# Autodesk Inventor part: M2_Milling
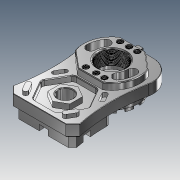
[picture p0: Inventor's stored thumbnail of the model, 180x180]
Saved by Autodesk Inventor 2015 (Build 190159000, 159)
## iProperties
Created: 2015-04
Part Number: M2_Milling
Material: Aço
Document SubType Name: Modeling
Designer: Andrew Almeida
Density: 7.85 g/cm^3
Appearance: Placa
Title: C:/Users/Andrew Almeida/Documents/Projeto WS2015/WS2015 CAD Data ANLAS/07/#07 - CNC Milling/01 - 3D Models/M2_Milling.stp
Creation Date: 2015-04-23
Sending System: Autodesk Translation Framework v4.0.0.5211
Preprocessor: ST-DEVELOPER v16.1
Author: Andrew Almeida
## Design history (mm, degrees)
node "M2_Milling1"
feature "Rosca1" dims "d0" = 10, "d1" = 0
feature "Rosca2" dims "d2" = 10, "d3" = 0
feature "Rosca3" dims "d4" = 10, "d5" = 0
feature "Rosca4" dims "d6" = 10, "d7" = 0
feature "Rosca5" dims "d8" = 10, "d9" = 0
feature "Rosca6" dims "d10" = 10, "d11" = 0
feature "Rosca7" dims "d12" = 20, "d13" = 0
feature "Rosca8" dims "d14" = 10, "d15" = 0
feature "Rosca9" dims "d16" = 10, "d17" = 0
feature "Rosca10" dims "d18" = 10, "d19" = 0
sketch "Esboço2"
  geometry: L1 (4.188, 0)-(4.188, 22); L2 (4.188, 22)-(3.447, 22); L3 (3.447, 22)-(3.447, 0); L4 (3.447, 0)-(4.188, 0); L5 (0, -10.409)-(0, 54.818) reference
  constraints: 8 end point
revolve "Revolução1" sketch "Esboço2" stored, may be unused: angle "d29" = 0 deg
sketch "Esboço1"
  geometry: L1 (-0.583, -0.051)-(-0.5, -0.051); L2 (0.083, -0.691)-(0, -0.851); L3 (-1, -0.851)-(-1.083, -0.691); L4 (-0.417, -0.051)-(-0.5, 0.109); L5 (-0.5, 0.109)-(-0.583, -0.051); L6 (-1, -0.851)-(-0.917, -0.691); L7 (-0.417, -0.051)-(-0.083, -0.691); L8 (-1.083, -0.691)-(-0.917, -0.691); L9 (0.083, -0.691)-(-0.083, -0.691); L10 (-1, -0.851)-(-1, -0.691); L11 (0, -0.851)-(0, -0.691); L12 (-0.5, 0.109)-(-0.5, 0); L13 (-1, -0.742)-(0, -0.742); L14 (-0.083, -0.691)-(0, -0.851); L15 (-0.917, -0.691)-(-0.583, -0.051); L16 (0, 0)-(0, 0.018); L17 (0, 0.018)-(0, 0); L18 (0, 0)-(0.033, 0); L19 (-0.5, 0)-(-0.5, -0.051); L20 (-0.5, -0.051)-(-0.417, -0.051); A1 r 0.094 centre (-1, -0.648) between (-1.083, -0.691) and (-1, -0.742); A2 r 0.094 centre (-1, -0.648) between (-1, -0.742) and (-0.917, -0.691); A3 r 0.094 centre (0, -0.648) between (-0.083, -0.691) and (0, -0.742); A4 r 0.094 centre (0, -0.648) between (0, -0.742) and (0.083, -0.691); A5 r 0.094 centre (-0.5, -0.094) between (-0.5, 0) and (-0.583, -0.051); A6 r 0.094 centre (-0.5, -0.094) between (-0.417, -0.051) and (-0.5, 0)
  constraints: 40 end point, 12 point on circle, 10 parallel, 8 tangent, 6 centre point, 6 collinear, 2 midpoint, 2 point on line, 1 horizontal, 1 perpendicular, 3 other
  dimensions: "d20" = 55 deg angle of L7 L15 (= d27); "d21" = 0.16008 distance of L4.end L1.end (= 0.160083 x Esboço1_Pitch); "d22" = 0.16008 distance of L2.end L11.end (= 0.160083 x Esboço1_Pitch); "Esboço1_ThreadOffset" = 0 distance between parallel lines of L16 L11; "Esboço1_MajorRadius" = 0.74146 distance from line of L13 L16.start; "d25" = 1 distance from line of L2.end L10 (= Esboço1_Pitch); "Esboço1_MinorRadius" = 0 distance edge to line of A6 L18 (derived)
feature "Espiral1" sketch "Esboço1" pitch "d30" = 1.5015; turns "d32" = 1; dims "d31" = 25, "d33" = 0, angle "d34" = 0 deg, angle "d35" = 0 deg, "d36" = 0, "d37" = 0
sketch "Esboço4"
  geometry: L1 (4.188, 0)-(4.188, 22); L2 (4.188, 22)-(3.447, 22); L3 (3.447, 22)-(3.447, 0); L4 (3.447, 0)-(4.188, 0); L5 (0, -10.409)-(0, 54.818) reference
  constraints: 8 end point
revolve "Revolução2" sketch "Esboço4" stored, may be unused: angle "d47" = 0 deg
sketch "Esboço3"
  geometry: L1 (-0.583, -0.051)-(-0.5, -0.051); L2 (0.083, -0.691)-(0, -0.851); L3 (-1, -0.851)-(-1.083, -0.691); L4 (-0.417, -0.051)-(-0.5, 0.109); L5 (-0.5, 0.109)-(-0.583, -0.051); L6 (-1, -0.851)-(-0.917, -0.691); L7 (-0.417, -0.051)-(-0.083, -0.691); L8 (-1.083, -0.691)-(-0.917, -0.691); L9 (0.083, -0.691)-(-0.083, -0.691); L10 (-1, -0.851)-(-1, -0.691); L11 (0, -0.851)-(0, -0.691); L12 (-0.5, 0.109)-(-0.5, 0); L13 (-1, -0.742)-(0, -0.742); L14 (-0.083, -0.691)-(0, -0.851); L15 (-0.917, -0.691)-(-0.583, -0.051); L16 (0, 0)-(0, 0.018); L17 (0, 0.018)-(0, 0); L18 (0, 0)-(0.033, 0); L19 (-0.5, 0)-(-0.5, -0.051); L20 (-0.5, -0.051)-(-0.417, -0.051); A1 r 0.094 centre (-1, -0.648) between (-1.083, -0.691) and (-1, -0.742); A2 r 0.094 centre (-1, -0.648) between (-1, -0.742) and (-0.917, -0.691); A3 r 0.094 centre (0, -0.648) between (-0.083, -0.691) and (0, -0.742); A4 r 0.094 centre (0, -0.648) between (0, -0.742) and (0.083, -0.691); A5 r 0.094 centre (-0.5, -0.094) between (-0.5, 0) and (-0.583, -0.051); A6 r 0.094 centre (-0.5, -0.094) between (-0.417, -0.051) and (-0.5, 0)
  constraints: 40 end point, 12 point on circle, 10 parallel, 8 tangent, 6 centre point, 6 collinear, 2 midpoint, 2 point on line, 1 horizontal, 1 perpendicular, 3 other
  dimensions: "d38" = 55 deg angle of L7 L15 (= d45); "d39" = 0.16008 distance of L4.end L1.end (= 0.160083 x Esboço3_Pitch); "d40" = 0.16008 distance of L2.end L11.end (= 0.160083 x Esboço3_Pitch); "Esboço3_ThreadOffset" = 0 distance between parallel lines of L16 L11; "Esboço3_MajorRadius" = 0.74146 distance from line of L13 L16.start; "d43" = 1 distance from line of L2.end L10 (= Esboço3_Pitch); "Esboço3_MinorRadius" = 0 distance edge to line of A6 L18 (derived)
feature "Espiral2" sketch "Esboço3" pitch "d48" = 1.5015; turns "d50" = 1; dims "d49" = 25, "d51" = 0, angle "d52" = 0 deg, angle "d53" = 0 deg, "d54" = 0, "d55" = 0
sketch "Esboço6"
  geometry: L1 (4.188, 0)-(4.188, 22); L2 (4.188, 22)-(3.447, 22); L3 (3.447, 22)-(3.447, 0); L4 (3.447, 0)-(4.188, 0); L5 (0, -10.409)-(0, 54.818) reference
  constraints: 8 end point
revolve "Revolução3" sketch "Esboço6" stored, may be unused: angle "d65" = 0 deg
sketch "Esboço5"
  geometry: L1 (-0.583, -0.051)-(-0.5, -0.051); L2 (0.083, -0.691)-(0, -0.851); L3 (-1, -0.851)-(-1.083, -0.691); L4 (-0.417, -0.051)-(-0.5, 0.109); L5 (-0.5, 0.109)-(-0.583, -0.051); L6 (-1, -0.851)-(-0.917, -0.691); L7 (-0.417, -0.051)-(-0.083, -0.691); L8 (-1.083, -0.691)-(-0.917, -0.691); L9 (0.083, -0.691)-(-0.083, -0.691); L10 (-1, -0.851)-(-1, -0.691); L11 (0, -0.851)-(0, -0.691); L12 (-0.5, 0.109)-(-0.5, 0); L13 (-1, -0.742)-(0, -0.742); L14 (-0.083, -0.691)-(0, -0.851); L15 (-0.917, -0.691)-(-0.583, -0.051); L16 (0, 0)-(0, 0.018); L17 (0, 0.018)-(0, 0); L18 (0, 0)-(0.033, 0); L19 (-0.5, 0)-(-0.5, -0.051); L20 (-0.5, -0.051)-(-0.417, -0.051); A1 r 0.094 centre (-1, -0.648) between (-1.083, -0.691) and (-1, -0.742); A2 r 0.094 centre (-1, -0.648) between (-1, -0.742) and (-0.917, -0.691); A3 r 0.094 centre (0, -0.648) between (-0.083, -0.691) and (0, -0.742); A4 r 0.094 centre (0, -0.648) between (0, -0.742) and (0.083, -0.691); A5 r 0.094 centre (-0.5, -0.094) between (-0.5, 0) and (-0.583, -0.051); A6 r 0.094 centre (-0.5, -0.094) between (-0.417, -0.051) and (-0.5, 0)
  constraints: 40 end point, 12 point on circle, 10 parallel, 8 tangent, 6 centre point, 6 collinear, 2 midpoint, 2 point on line, 1 horizontal, 1 perpendicular, 3 other
  dimensions: "d56" = 55 deg angle of L7 L15 (= d63); "d57" = 0.16008 distance of L4.end L1.end (= 0.160083 x Esboço5_Pitch); "d58" = 0.16008 distance of L2.end L11.end (= 0.160083 x Esboço5_Pitch); "Esboço5_ThreadOffset" = 0 distance between parallel lines of L16 L11; "Esboço5_MajorRadius" = 0.74146 distance from line of L13 L16.start; "d61" = 1 distance from line of L2.end L10 (= Esboço5_Pitch); "Esboço5_MinorRadius" = 0 distance edge to line of A6 L18 (derived)
feature "Espiral3" sketch "Esboço5" pitch "d66" = 1.5015; turns "d68" = 1; dims "d67" = 25, "d69" = 0, angle "d70" = 0 deg, angle "d71" = 0 deg, "d72" = 0, "d73" = 0
sketch "Esboço8"
  geometry: L1 (4.188, 0)-(4.188, 22); L2 (4.188, 22)-(3.447, 22); L3 (3.447, 22)-(3.447, 0); L4 (3.447, 0)-(4.188, 0); L5 (0, -10.409)-(0, 54.818) reference
  constraints: 8 end point
revolve "Revolução4" sketch "Esboço8" stored, may be unused: angle "d83" = 0 deg
sketch "Esboço7"
  geometry: L1 (-0.583, -0.051)-(-0.5, -0.051); L2 (0.083, -0.691)-(0, -0.851); L3 (-1, -0.851)-(-1.083, -0.691); L4 (-0.417, -0.051)-(-0.5, 0.109); L5 (-0.5, 0.109)-(-0.583, -0.051); L6 (-1, -0.851)-(-0.917, -0.691); L7 (-0.417, -0.051)-(-0.083, -0.691); L8 (-1.083, -0.691)-(-0.917, -0.691); L9 (0.083, -0.691)-(-0.083, -0.691); L10 (-1, -0.851)-(-1, -0.691); L11 (0, -0.851)-(0, -0.691); L12 (-0.5, 0.109)-(-0.5, 0); L13 (-1, -0.742)-(0, -0.742); L14 (-0.083, -0.691)-(0, -0.851); L15 (-0.917, -0.691)-(-0.583, -0.051); L16 (0, 0)-(0, 0.018); L17 (0, 0.018)-(0, 0); L18 (0, 0)-(0.033, 0); L19 (-0.5, 0)-(-0.5, -0.051); L20 (-0.5, -0.051)-(-0.417, -0.051); A1 r 0.094 centre (-1, -0.648) between (-1.083, -0.691) and (-1, -0.742); A2 r 0.094 centre (-1, -0.648) between (-1, -0.742) and (-0.917, -0.691); A3 r 0.094 centre (0, -0.648) between (-0.083, -0.691) and (0, -0.742); A4 r 0.094 centre (0, -0.648) between (0, -0.742) and (0.083, -0.691); A5 r 0.094 centre (-0.5, -0.094) between (-0.5, 0) and (-0.583, -0.051); A6 r 0.094 centre (-0.5, -0.094) between (-0.417, -0.051) and (-0.5, 0)
  constraints: 40 end point, 12 point on circle, 10 parallel, 8 tangent, 6 centre point, 6 collinear, 2 midpoint, 2 point on line, 1 horizontal, 1 perpendicular, 3 other
  dimensions: "d74" = 55 deg angle of L7 L15 (= d81); "d75" = 0.16008 distance of L4.end L1.end (= 0.160083 x Esboço7_Pitch); "d76" = 0.16008 distance of L2.end L11.end (= 0.160083 x Esboço7_Pitch); "Esboço7_ThreadOffset" = 0 distance between parallel lines of L16 L11; "Esboço7_MajorRadius" = 0.74146 distance from line of L13 L16.start; "d79" = 1 distance from line of L2.end L10 (= Esboço7_Pitch); "Esboço7_MinorRadius" = 0 distance edge to line of A6 L18 (derived)
feature "Espiral4" sketch "Esboço7" pitch "d84" = 1.5015; turns "d86" = 1; dims "d85" = 25, "d87" = 0, angle "d88" = 0 deg, angle "d89" = 0 deg, "d90" = 0, "d91" = 0
sketch "Esboço10"
  geometry: L1 (4.188, 0)-(4.188, 22); L2 (4.188, 22)-(3.447, 22); L3 (3.447, 22)-(3.447, 0); L4 (3.447, 0)-(4.188, 0); L5 (0, -10.409)-(0, 54.818) reference
  constraints: 8 end point
revolve "Revolução5" sketch "Esboço10" stored, may be unused: angle "d101" = 0 deg
sketch "Esboço9"
  geometry: L1 (-0.583, -0.051)-(-0.5, -0.051); L2 (0.083, -0.691)-(0, -0.851); L3 (-1, -0.851)-(-1.083, -0.691); L4 (-0.417, -0.051)-(-0.5, 0.109); L5 (-0.5, 0.109)-(-0.583, -0.051); L6 (-1, -0.851)-(-0.917, -0.691); L7 (-0.417, -0.051)-(-0.083, -0.691); L8 (-1.083, -0.691)-(-0.917, -0.691); L9 (0.083, -0.691)-(-0.083, -0.691); L10 (-1, -0.851)-(-1, -0.691); L11 (0, -0.851)-(0, -0.691); L12 (-0.5, 0.109)-(-0.5, 0); L13 (-1, -0.742)-(0, -0.742); L14 (-0.083, -0.691)-(0, -0.851); L15 (-0.917, -0.691)-(-0.583, -0.051); L16 (0, 0)-(0, 0.018); L17 (0, 0.018)-(0, 0); L18 (0, 0)-(0.033, 0); L19 (-0.5, 0)-(-0.5, -0.051); L20 (-0.5, -0.051)-(-0.417, -0.051); A1 r 0.094 centre (-1, -0.648) between (-1.083, -0.691) and (-1, -0.742); A2 r 0.094 centre (-1, -0.648) between (-1, -0.742) and (-0.917, -0.691); A3 r 0.094 centre (0, -0.648) between (-0.083, -0.691) and (0, -0.742); A4 r 0.094 centre (0, -0.648) between (0, -0.742) and (0.083, -0.691); A5 r 0.094 centre (-0.5, -0.094) between (-0.5, 0) and (-0.583, -0.051); A6 r 0.094 centre (-0.5, -0.094) between (-0.417, -0.051) and (-0.5, 0)
  constraints: 40 end point, 12 point on circle, 10 parallel, 8 tangent, 6 centre point, 6 collinear, 2 midpoint, 2 point on line, 1 horizontal, 1 perpendicular, 3 other
  dimensions: "d92" = 55 deg angle of L7 L15 (= d99); "d93" = 0.16008 distance of L4.end L1.end (= 0.160083 x Esboço9_Pitch); "d94" = 0.16008 distance of L2.end L11.end (= 0.160083 x Esboço9_Pitch); "Esboço9_ThreadOffset" = 0 distance between parallel lines of L16 L11; "Esboço9_MajorRadius" = 0.74146 distance from line of L13 L16.start; "d97" = 1 distance from line of L2.end L10 (= Esboço9_Pitch); "Esboço9_MinorRadius" = 0 distance edge to line of A6 L18 (derived)
feature "Espiral5" sketch "Esboço9" pitch "d102" = 1.5015; turns "d104" = 1; dims "d103" = 25, "d105" = 0, angle "d106" = 0 deg, angle "d107" = 0 deg, "d108" = 0, "d109" = 0
sketch "Esboço12"
  geometry: L1 (4.188, 0)-(4.188, 22); L2 (4.188, 22)-(3.447, 22); L3 (3.447, 22)-(3.447, 0); L4 (3.447, 0)-(4.188, 0); L5 (0, -10.409)-(0, 54.818) reference
  constraints: 8 end point
revolve "Revolução6" sketch "Esboço12" stored, may be unused: angle "d119" = 0 deg
sketch "Esboço11"
  geometry: L1 (-0.583, -0.051)-(-0.5, -0.051); L2 (0.083, -0.691)-(0, -0.851); L3 (-1, -0.851)-(-1.083, -0.691); L4 (-0.417, -0.051)-(-0.5, 0.109); L5 (-0.5, 0.109)-(-0.583, -0.051); L6 (-1, -0.851)-(-0.917, -0.691); L7 (-0.417, -0.051)-(-0.083, -0.691); L8 (-1.083, -0.691)-(-0.917, -0.691); L9 (0.083, -0.691)-(-0.083, -0.691); L10 (-1, -0.851)-(-1, -0.691); L11 (0, -0.851)-(0, -0.691); L12 (-0.5, 0.109)-(-0.5, 0); L13 (-1, -0.742)-(0, -0.742); L14 (-0.083, -0.691)-(0, -0.851); L15 (-0.917, -0.691)-(-0.583, -0.051); L16 (0, 0)-(0, 0.018); L17 (0, 0.018)-(0, 0); L18 (0, 0)-(0.033, 0); L19 (-0.5, 0)-(-0.5, -0.051); L20 (-0.5, -0.051)-(-0.417, -0.051); A1 r 0.094 centre (-1, -0.648) between (-1.083, -0.691) and (-1, -0.742); A2 r 0.094 centre (-1, -0.648) between (-1, -0.742) and (-0.917, -0.691); A3 r 0.094 centre (0, -0.648) between (-0.083, -0.691) and (0, -0.742); A4 r 0.094 centre (0, -0.648) between (0, -0.742) and (0.083, -0.691); A5 r 0.094 centre (-0.5, -0.094) between (-0.5, 0) and (-0.583, -0.051); A6 r 0.094 centre (-0.5, -0.094) between (-0.417, -0.051) and (-0.5, 0)
  constraints: 40 end point, 12 point on circle, 10 parallel, 8 tangent, 6 centre point, 6 collinear, 2 midpoint, 2 point on line, 1 horizontal, 1 perpendicular, 3 other
  dimensions: "d110" = 55 deg angle of L7 L15 (= d117); "d111" = 0.16008 distance of L4.end L1.end (= 0.160083 x Esboço11_Pitch); "d112" = 0.16008 distance of L2.end L11.end (= 0.160083 x Esboço11_Pitch); "Esboço11_ThreadOffset" = 0 distance between parallel lines of L16 L11; "Esboço11_MajorRadius" = 0.74146 distance from line of L13 L16.start; "d115" = 1 distance from line of L2.end L10 (= Esboço11_Pitch); "Esboço11_MinorRadius" = 0 distance edge to line of A6 L18 (derived)
feature "Espiral6" sketch "Esboço11" pitch "d120" = 1.5015; turns "d122" = 1; dims "d121" = 25, "d123" = 0, angle "d124" = 0 deg, angle "d125" = 0 deg, "d126" = 0, "d127" = 0
sketch "Esboço16"
  geometry: L1 (2.518, 0)-(2.518, 17.524); L2 (2.518, 17.524)-(1.776, 17.524); L3 (1.776, 17.524)-(1.776, 0); L4 (1.776, 0)-(2.518, 0); L5 (0, -13.608)-(0, 50.559) reference
  constraints: 8 end point
revolve "Revolução8" sketch "Esboço16" stored, may be unused: angle "d155" = 0 deg
sketch "Esboço15"
  geometry: L1 (-0.583, -0.051)-(-0.5, -0.051); L2 (0.083, -0.691)-(0, -0.851); L3 (-1, -0.851)-(-1.083, -0.691); L4 (-0.417, -0.051)-(-0.5, 0.109); L5 (-0.5, 0.109)-(-0.583, -0.051); L6 (-1, -0.851)-(-0.917, -0.691); L7 (-0.417, -0.051)-(-0.083, -0.691); L8 (-1.083, -0.691)-(-0.917, -0.691); L9 (0.083, -0.691)-(-0.083, -0.691); L10 (-1, -0.851)-(-1, -0.691); L11 (0, -0.851)-(0, -0.691); L12 (-0.5, 0.109)-(-0.5, 0); L13 (-1, -0.742)-(0, -0.742); L14 (-0.083, -0.691)-(0, -0.851); L15 (-0.917, -0.691)-(-0.583, -0.051); L16 (0, 0)-(0, 0.018); L17 (0, 0.018)-(0, 0); L18 (0, 0)-(0.033, 0); L19 (-0.5, 0)-(-0.5, -0.051); L20 (-0.5, -0.051)-(-0.417, -0.051); A1 r 0.094 centre (-1, -0.648) between (-1.083, -0.691) and (-1, -0.742); A2 r 0.094 centre (-1, -0.648) between (-1, -0.742) and (-0.917, -0.691); A3 r 0.094 centre (0, -0.648) between (-0.083, -0.691) and (0, -0.742); A4 r 0.094 centre (0, -0.648) between (0, -0.742) and (0.083, -0.691); A5 r 0.094 centre (-0.5, -0.094) between (-0.5, 0) and (-0.583, -0.051); A6 r 0.094 centre (-0.5, -0.094) between (-0.417, -0.051) and (-0.5, 0)
  constraints: 40 end point, 12 point on circle, 10 parallel, 8 tangent, 6 centre point, 6 collinear, 2 midpoint, 2 point on line, 1 horizontal, 1 perpendicular, 3 other
  dimensions: "d146" = 55 deg angle of L7 L15 (= d153); "d147" = 0.16008 distance of L4.end L1.end (= 0.160083 x Esboço15_Pitch); "d148" = 0.16008 distance of L2.end L11.end (= 0.160083 x Esboço15_Pitch); "Esboço15_ThreadOffset" = 0 distance between parallel lines of L16 L11; "Esboço15_MajorRadius" = 0.74146 distance from line of L13 L16.start; "d151" = 1 distance from line of L2.end L10 (= Esboço15_Pitch); "Esboço15_MinorRadius" = 0 distance edge to line of A6 L18 (derived)
feature "Espiral8" sketch "Esboço15" pitch "d156" = 1.001; turns "d158" = 1; dims "d157" = 19.52355, "d159" = 0, angle "d160" = 0 deg, angle "d161" = 0 deg, "d162" = 0, "d163" = 0
sketch "Esboço18"
  geometry: L1 (2.517, 0)-(2.517, 17.524); L2 (2.517, 17.524)-(1.776, 17.524); L3 (1.776, 17.524)-(1.776, 0); L4 (1.776, 0)-(2.517, 0); L5 (0, -13.608)-(0, 50.559) reference
  constraints: 8 end point
revolve "Revolução9" sketch "Esboço18" stored, may be unused: angle "d173" = 0 deg
sketch "Esboço17"
  geometry: L1 (-0.583, -0.051)-(-0.5, -0.051); L2 (0.083, -0.691)-(0, -0.851); L3 (-1, -0.851)-(-1.083, -0.691); L4 (-0.417, -0.051)-(-0.5, 0.109); L5 (-0.5, 0.109)-(-0.583, -0.051); L6 (-1, -0.851)-(-0.917, -0.691); L7 (-0.417, -0.051)-(-0.083, -0.691); L8 (-1.083, -0.691)-(-0.917, -0.691); L9 (0.083, -0.691)-(-0.083, -0.691); L10 (-1, -0.851)-(-1, -0.691); L11 (0, -0.851)-(0, -0.691); L12 (-0.5, 0.109)-(-0.5, 0); L13 (-1, -0.742)-(0, -0.742); L14 (-0.083, -0.691)-(0, -0.851); L15 (-0.917, -0.691)-(-0.583, -0.051); L16 (0, 0)-(0, 0.018); L17 (0, 0.018)-(0, 0); L18 (0, 0)-(0.033, 0); L19 (-0.5, 0)-(-0.5, -0.051); L20 (-0.5, -0.051)-(-0.417, -0.051); A1 r 0.094 centre (-1, -0.648) between (-1.083, -0.691) and (-1, -0.742); A2 r 0.094 centre (-1, -0.648) between (-1, -0.742) and (-0.917, -0.691); A3 r 0.094 centre (0, -0.648) between (-0.083, -0.691) and (0, -0.742); A4 r 0.094 centre (0, -0.648) between (0, -0.742) and (0.083, -0.691); A5 r 0.094 centre (-0.5, -0.094) between (-0.5, 0) and (-0.583, -0.051); A6 r 0.094 centre (-0.5, -0.094) between (-0.417, -0.051) and (-0.5, 0)
  constraints: 40 end point, 12 point on circle, 10 parallel, 8 tangent, 6 centre point, 6 collinear, 2 midpoint, 2 point on line, 1 horizontal, 1 perpendicular, 3 other
  dimensions: "d164" = 55 deg angle of L7 L15 (= d171); "d165" = 0.16008 distance of L4.end L1.end (= 0.160083 x Esboço17_Pitch); "d166" = 0.16008 distance of L2.end L11.end (= 0.160083 x Esboço17_Pitch); "Esboço17_ThreadOffset" = 0 distance between parallel lines of L16 L11; "Esboço17_MajorRadius" = 0.74146 distance from line of L13 L16.start; "d169" = 1 distance from line of L2.end L10 (= Esboço17_Pitch); "Esboço17_MinorRadius" = 0 distance edge to line of A6 L18 (derived)
feature "Espiral9" sketch "Esboço17" pitch "d174" = 1.001; turns "d176" = 1; dims "d175" = 19.52355, "d177" = 0, angle "d178" = 0 deg, angle "d179" = 0 deg, "d180" = 0, "d181" = 0
sketch "Esboço20"
  geometry: L1 (2.518, 0)-(2.518, 17.524); L2 (2.518, 17.524)-(1.776, 17.524); L3 (1.776, 17.524)-(1.776, 0); L4 (1.776, 0)-(2.518, 0); L5 (0, -13.608)-(0, 50.559) reference
  constraints: 8 end point
revolve "Revolução10" sketch "Esboço20" stored, may be unused: angle "d191" = 0 deg
sketch "Esboço19"
  geometry: L1 (-0.583, -0.051)-(-0.5, -0.051); L2 (0.083, -0.691)-(0, -0.851); L3 (-1, -0.851)-(-1.083, -0.691); L4 (-0.417, -0.051)-(-0.5, 0.109); L5 (-0.5, 0.109)-(-0.583, -0.051); L6 (-1, -0.851)-(-0.917, -0.691); L7 (-0.417, -0.051)-(-0.083, -0.691); L8 (-1.083, -0.691)-(-0.917, -0.691); L9 (0.083, -0.691)-(-0.083, -0.691); L10 (-1, -0.851)-(-1, -0.691); L11 (0, -0.851)-(0, -0.691); L12 (-0.5, 0.109)-(-0.5, 0); L13 (-1, -0.742)-(0, -0.742); L14 (-0.083, -0.691)-(0, -0.851); L15 (-0.917, -0.691)-(-0.583, -0.051); L16 (0, 0)-(0, 0.018); L17 (0, 0.018)-(0, 0); L18 (0, 0)-(0.033, 0); L19 (-0.5, 0)-(-0.5, -0.051); L20 (-0.5, -0.051)-(-0.417, -0.051); A1 r 0.094 centre (-1, -0.648) between (-1.083, -0.691) and (-1, -0.742); A2 r 0.094 centre (-1, -0.648) between (-1, -0.742) and (-0.917, -0.691); A3 r 0.094 centre (0, -0.648) between (-0.083, -0.691) and (0, -0.742); A4 r 0.094 centre (0, -0.648) between (0, -0.742) and (0.083, -0.691); A5 r 0.094 centre (-0.5, -0.094) between (-0.5, 0) and (-0.583, -0.051); A6 r 0.094 centre (-0.5, -0.094) between (-0.417, -0.051) and (-0.5, 0)
  constraints: 40 end point, 12 point on circle, 10 parallel, 8 tangent, 6 centre point, 6 collinear, 2 midpoint, 2 point on line, 1 horizontal, 1 perpendicular, 3 other
  dimensions: "d182" = 55 deg angle of L7 L15 (= d189); "d183" = 0.16008 distance of L4.end L1.end (= 0.160083 x Esboço19_Pitch); "d184" = 0.16008 distance of L2.end L11.end (= 0.160083 x Esboço19_Pitch); "Esboço19_ThreadOffset" = 0 distance between parallel lines of L16 L11; "Esboço19_MajorRadius" = 0.74146 distance from line of L13 L16.start; "d187" = 1 distance from line of L2.end L10 (= Esboço19_Pitch); "Esboço19_MinorRadius" = 0 distance edge to line of A6 L18 (derived)
feature "Espiral10" sketch "Esboço19" pitch "d192" = 1.001; turns "d194" = 1; dims "d193" = 19.52355, "d195" = 0, angle "d196" = 0 deg, angle "d197" = 0 deg, "d198" = 0, "d199" = 0
sketch "Esboço22"
  geometry: L1 (20.263, 0)-(20.263, 20); L2 (20.263, 20)-(19.522, 20); L3 (19.522, 20)-(19.522, 0); L4 (19.522, 0)-(20.263, 0); L5 (0, -10.925)-(0, 53.242) reference
  constraints: 8 end point
revolve "Revolução11" sketch "Esboço22" stored, may be unused: angle "d209" = 0 deg
sketch "Esboço21"
  geometry: L1 (-0.583, -0.051)-(-0.5, -0.051); L2 (0.083, -0.691)-(0, -0.851); L3 (-1, -0.851)-(-1.083, -0.691); L4 (-0.417, -0.051)-(-0.5, 0.109); L5 (-0.5, 0.109)-(-0.583, -0.051); L6 (-1, -0.851)-(-0.917, -0.691); L7 (-0.417, -0.051)-(-0.083, -0.691); L8 (-1.083, -0.691)-(-0.917, -0.691); L9 (0.083, -0.691)-(-0.083, -0.691); L10 (-1, -0.851)-(-1, -0.691); L11 (0, -0.851)-(0, -0.691); L12 (-0.5, 0.109)-(-0.5, 0); L13 (-1, -0.742)-(0, -0.742); L14 (-0.083, -0.691)-(0, -0.851); L15 (-0.917, -0.691)-(-0.583, -0.051); L16 (0, 0)-(0, 0.018); L17 (0, 0.018)-(0, 0); L18 (0, 0)-(0.033, 0); L19 (-0.5, 0)-(-0.5, -0.051); L20 (-0.5, -0.051)-(-0.417, -0.051); A1 r 0.094 centre (-1, -0.648) between (-1.083, -0.691) and (-1, -0.742); A2 r 0.094 centre (-1, -0.648) between (-1, -0.742) and (-0.917, -0.691); A3 r 0.094 centre (0, -0.648) between (-0.083, -0.691) and (0, -0.742); A4 r 0.094 centre (0, -0.648) between (0, -0.742) and (0.083, -0.691); A5 r 0.094 centre (-0.5, -0.094) between (-0.5, 0) and (-0.583, -0.051); A6 r 0.094 centre (-0.5, -0.094) between (-0.417, -0.051) and (-0.5, 0)
  constraints: 40 end point, 12 point on circle, 10 parallel, 8 tangent, 6 centre point, 6 collinear, 2 midpoint, 2 point on line, 1 horizontal, 1 perpendicular, 3 other
  dimensions: "d200" = 55 deg angle of L7 L15 (= d207); "d201" = 0.16008 distance of L4.end L1.end (= 0.160083 x Esboço21_Pitch); "d202" = 0.16008 distance of L2.end L11.end (= 0.160083 x Esboço21_Pitch); "Esboço21_ThreadOffset" = 0 distance between parallel lines of L16 L11; "Esboço21_MajorRadius" = 0.74146 distance from line of L13 L16.start; "d205" = 1 distance from line of L2.end L10 (= Esboço21_Pitch); "Esboço21_MinorRadius" = 0 distance edge to line of A6 L18 (derived)
feature "Espiral11" sketch "Esboço21" pitch "d210" = 1.5015; turns "d212" = 1; dims "d211" = 23, "d213" = 0, angle "d214" = 0 deg, angle "d215" = 0 deg, "d216" = 0, "d217" = 0
node "Body1"
node "Base1"
node "Sólido2"
node "Sólido3"
node "Sólido4"
node "Sólido5"
node "Sólido6"
node "Sólido7"
node "Sólido9"
node "Sólido10"
node "Sólido11"
node "Sólido12"
other parameters: "d27" = 55 deg [user parameter; used in 1 equation term], "Esboço1_Pitch" = 1 [user parameter; used in 3 equation terms], "d45" = 55 deg [user parameter; used in 1 equation term], "Esboço3_Pitch" = 1 [user parameter; used in 3 equation terms], "d63" = 55 deg [user parameter; used in 1 equation term], "Esboço5_Pitch" = 1 [user parameter; used in 3 equation terms], "d81" = 55 deg [user parameter; used in 1 equation term], "Esboço7_Pitch" = 1 [user parameter; used in 3 equation terms], "d99" = 55 deg [user parameter; used in 1 equation term], "Esboço9_Pitch" = 1 [user parameter; used in 3 equation terms], "d117" = 55 deg [user parameter; used in 1 equation term], "Esboço11_Pitch" = 1 [user parameter; used in 3 equation terms], "d135" = 55 deg [user parameter], "Esboço13_Pitch" = 1 [user parameter], "d153" = 55 deg [user parameter; used in 1 equation term], "Esboço15_Pitch" = 1 [user parameter; used in 3 equation terms], "d171" = 55 deg [user parameter; used in 1 equation term], "Esboço17_Pitch" = 1 [user parameter; used in 3 equation terms], "d189" = 55 deg [user parameter; used in 1 equation term], "Esboço19_Pitch" = 1 [user parameter; used in 3 equation terms], "d207" = 55 deg [user parameter; used in 1 equation term], "Esboço21_Pitch" = 1 [user parameter; used in 3 equation terms]
